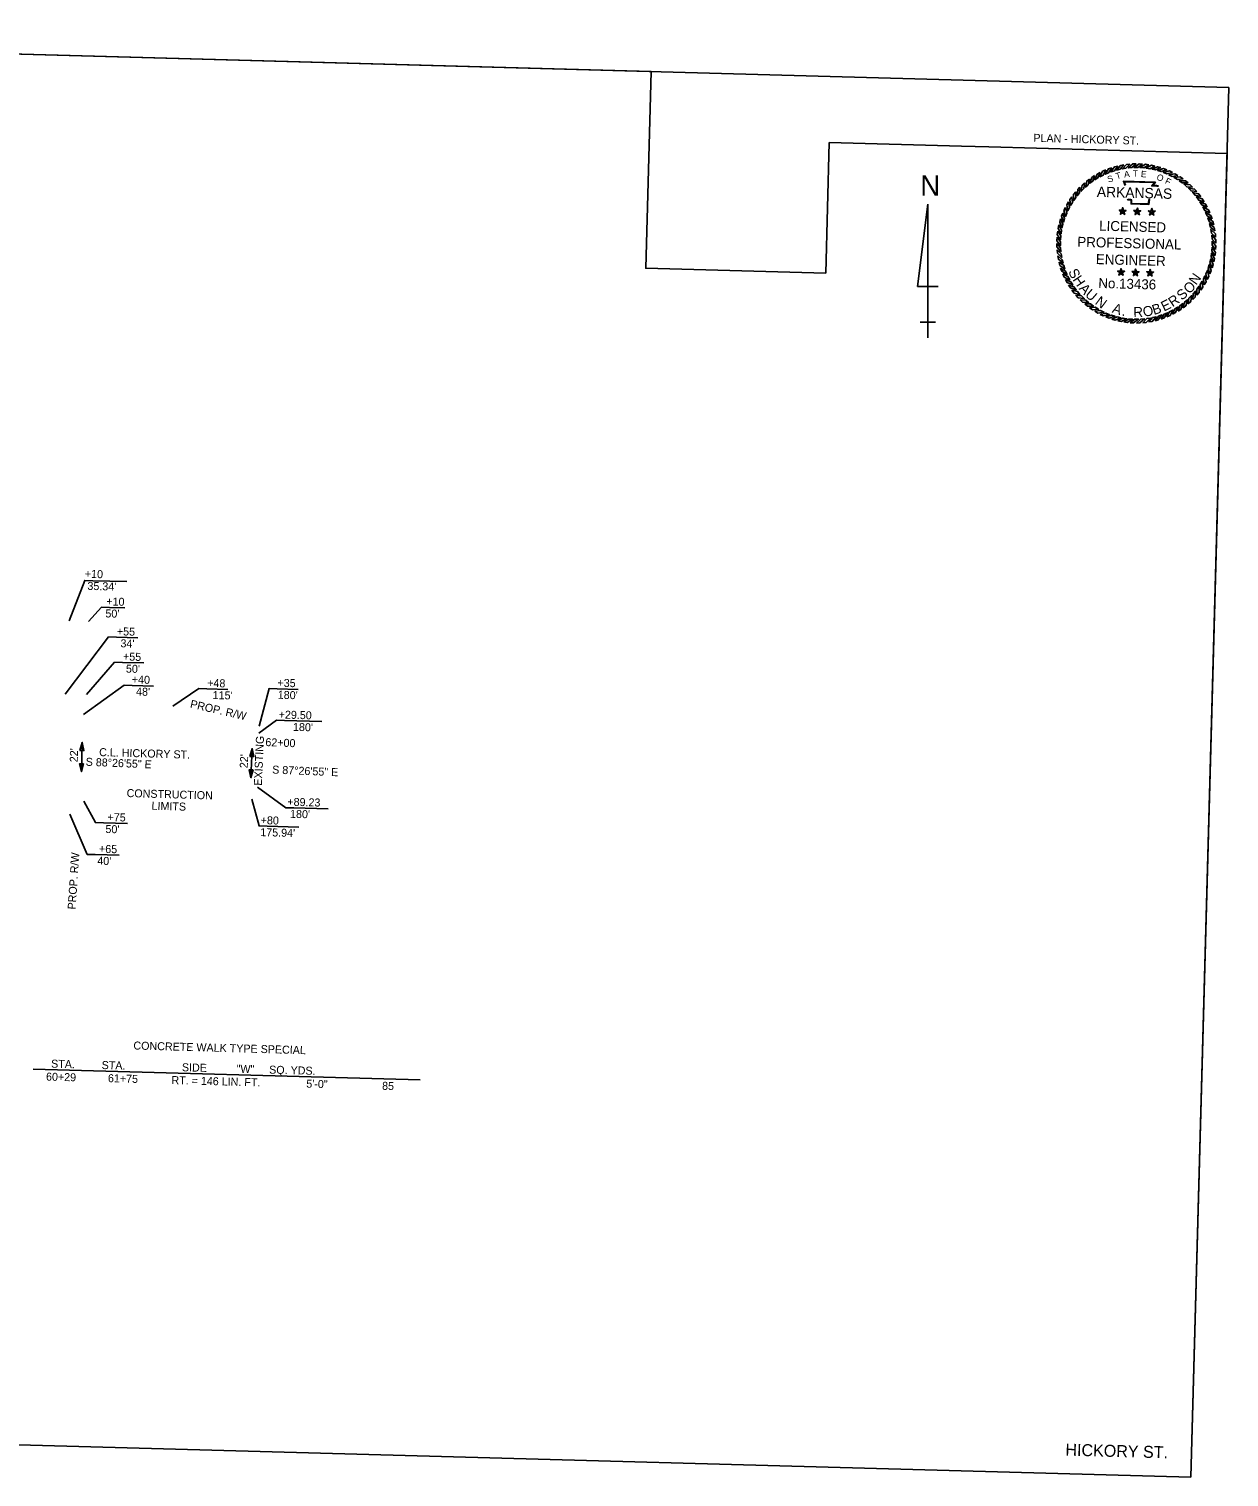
# Model space of a CAD drawing. Extents: x 991810 to 993433, y 1843620 to 1844706.
# Drawn here: x 992534 to 993433, y 1843620 to 1844706 of the extents above; entities that cross this region are included whole.
import ezdxf

# ---------------------------------------------------------------- set-up
doc = ezdxf.new("R2010")
doc.units = 0
for name, color, linetype in [('63', 7, 'Continuous'), ('8', 7, 'Continuous'), ('G-ANNO-SYMB', 7, 'Continuous'), ('G-ANNO-TEXT', 7, 'Continuous'), ('G-Border-Sheet', 7, 'Continuous'), ('G-No Plot-Border-2', 7, 'Continuous'), ('R_Draft', 7, 'Continuous'), ('R_Horz Alg Stationing', 7, 'Continuous')]:
    doc.layers.add(name, color=color, linetype=linetype)

msp = doc.modelspace()

# ---------------------------------------------------------------- linework, layer by layer
at = {"layer": '63'}
for p, q in [((993207.4, 1844574.4), (993199.7, 1844512.9)), ((993207.4, 1844474.4), (993207.4, 1844574.4)), ((993207.4, 1844574.4), (993207.4, 1844497.5)), ((993199.7, 1844512.9), (993215.1, 1844512.9)), ((993207.4, 1844474.4), (993207.4, 1844497.5)), ((993207.4, 1844486), (993201.6, 1844486)), ((993201.6, 1844486), (993213.2, 1844486)), ((993207.4, 1844474.4), (993207.4, 1844486))]:
    msp.add_line(p, q, dxfattribs=at)
at = {"layer": '8'}
msp.add_line((992536.8, 1843925.9), (992826.8, 1843917.9), dxfattribs=at)
at = {"layer": 'G-ANNO-SYMB'}
for points in [[(993345.3, 1844601.8), (993342.8, 1844601), (993340.5, 1844597), (993343, 1844598.1)], [(993349.8, 1844603.1), (993347.3, 1844602.4), (993344.6, 1844598.7), (993347.3, 1844599.6)], [(993354.4, 1844604), (993351.8, 1844603.5), (993348.9, 1844600.1), (993351.6, 1844600.7)], [(993359, 1844604.6), (993356.5, 1844604.3), (993353.3, 1844601), (993356, 1844601.5)], [(993363.7, 1844604.8), (993361.1, 1844604.7), (993357.7, 1844601.7), (993360.4, 1844601.9)], [(993368.4, 1844604.6), (993365.8, 1844604.7), (993362.1, 1844602), (993364.9, 1844602)], [(993373, 1844604), (993370.5, 1844604.4), (993366.6, 1844602), (993369.4, 1844601.7)], [(993377.6, 1844603.1), (993375.1, 1844603.7), (993371.1, 1844601.6), (993373.8, 1844601.1)], [(993382.1, 1844601.9), (993379.7, 1844602.6), (993375.5, 1844600.8), (993378.2, 1844600.2)], [(993386.5, 1844600.2), (993384.1, 1844601.2), (993379.8, 1844599.7), (993382.4, 1844598.9)], [(993325, 1844590.4), (993323.1, 1844588.7), (993322.4, 1844584.2), (993324.3, 1844586.2)], [(993328.6, 1844593.3), (993326.6, 1844591.8), (993325.6, 1844587.3), (993327.7, 1844589.1)], [(993332.5, 1844595.9), (993330.4, 1844594.5), (993329, 1844590.2), (993331.2, 1844591.8)], [(993336.6, 1844598.2), (993334.4, 1844597), (993332.6, 1844592.8), (993335, 1844594.2)], [(993340.9, 1844600.2), (993338.5, 1844599.2), (993336.5, 1844595.1), (993338.9, 1844596.3)], [(993390.8, 1844598.3), (993388.5, 1844599.4), (993384, 1844598.3), (993386.6, 1844597.2)], [(993394.9, 1844596), (993392.7, 1844597.3), (993388.2, 1844596.5), (993390.6, 1844595.3)], [(993398.8, 1844593.4), (993396.7, 1844594.9), (993392.1, 1844594.5), (993394.5, 1844593)], [(993402.5, 1844590.5), (993400.5, 1844592.1), (993395.9, 1844592.1), (993398.1, 1844590.5)], [(993315.5, 1844580.1), (993314, 1844578), (993314.4, 1844573.4), (993315.8, 1844575.8)], [(993318.4, 1844583.8), (993316.7, 1844581.8), (993316.8, 1844577.2), (993318.4, 1844579.5)], [(993321.5, 1844587.2), (993319.8, 1844585.4), (993319.4, 1844580.8), (993321.2, 1844582.9)], [(993405.9, 1844587.3), (993404, 1844589.1), (993399.5, 1844589.4), (993401.6, 1844587.6)], [(993409.1, 1844583.9), (993407.4, 1844585.8), (993402.9, 1844586.5), (993404.8, 1844584.5)], [(993412, 1844580.2), (993410.4, 1844582.3), (993406, 1844583.3), (993407.8, 1844581.2)], [(993414.6, 1844576.3), (993413.2, 1844578.5), (993408.8, 1844579.9), (993410.5, 1844577.6)], [(993310.6, 1844572.1), (993309.5, 1844569.8), (993310.6, 1844565.4), (993311.6, 1844567.9)], [(993312.9, 1844576.2), (993311.6, 1844574), (993312.3, 1844569.5), (993313.6, 1844572)], [(993353.5, 1844569.1), (993352.9, 1844570), (993350.9, 1844570.1), (993352.5, 1844568.8)], [(993353.5, 1844569.1), (993352.5, 1844568.8), (993351.8, 1844567), (993353.5, 1844568.1)], [(993353.5, 1844569.1), (993354.1, 1844570), (993353.6, 1844571.9), (993352.9, 1844570)], [(993353.5, 1844569.1), (993354.5, 1844568.8), (993356.1, 1844569.9), (993354.1, 1844570)], [(993353.5, 1844569.1), (993353.5, 1844568.1), (993355.1, 1844566.9), (993354.5, 1844568.8)], [(993364.4, 1844568.8), (993363.8, 1844569.7), (993361.8, 1844569.8), (993363.4, 1844568.5)], [(993364.4, 1844568.8), (993363.4, 1844568.5), (993362.8, 1844566.7), (993364.4, 1844567.8)], [(993364.4, 1844568.8), (993365.1, 1844569.7), (993364.5, 1844571.6), (993363.8, 1844569.7)], [(993364.4, 1844568.8), (993365.4, 1844568.5), (993367, 1844569.6), (993365.1, 1844569.7)], [(993364.4, 1844568.8), (993364.4, 1844567.8), (993366, 1844566.6), (993365.4, 1844568.5)], [(993375.3, 1844568.5), (993374.7, 1844569.4), (993372.8, 1844569.5), (993374.3, 1844568.2)], [(993375.3, 1844568.5), (993374.3, 1844568.2), (993373.7, 1844566.4), (993375.3, 1844567.5)], [(993375.3, 1844568.5), (993376, 1844569.4), (993375.4, 1844571.3), (993374.7, 1844569.4)], [(993375.3, 1844568.5), (993376.3, 1844568.2), (993377.9, 1844569.3), (993376, 1844569.4)], [(993375.3, 1844568.5), (993375.3, 1844567.5), (993376.9, 1844566.3), (993376.3, 1844568.2)], [(993416.9, 1844572.2), (993415.7, 1844574.5), (993411.4, 1844576.2), (993412.9, 1844573.9)], [(993418.9, 1844568), (993417.8, 1844570.3), (993413.7, 1844572.4), (993415, 1844569.9)], [(993305.7, 1844559), (993305.2, 1844556.4), (993307.3, 1844552.4), (993307.7, 1844555.1)], [(993307, 1844563.5), (993306.3, 1844561), (993308, 1844556.8), (993308.7, 1844559.5)], [(993308.6, 1844567.9), (993307.7, 1844565.5), (993309.1, 1844561.1), (993310, 1844563.8)], [(993420.5, 1844563.6), (993419.6, 1844566), (993415.7, 1844568.4), (993416.8, 1844565.8)], [(993421.8, 1844559.1), (993421.1, 1844561.6), (993417.4, 1844564.2), (993418.3, 1844561.6)], [(993422.7, 1844554.5), (993422.2, 1844557), (993418.7, 1844560), (993419.4, 1844557.3)], [(993304.3, 1844549.7), (993304.1, 1844547.1), (993306.9, 1844543.5), (993306.8, 1844546.2)], [(993304.8, 1844554.4), (993304.5, 1844551.8), (993306.9, 1844547.9), (993307.1, 1844550.7)], [(993423.2, 1844549.8), (993423, 1844552.4), (993419.7, 1844555.6), (993420.2, 1844552.9)], [(993423.4, 1844545.2), (993423.4, 1844547.7), (993420.4, 1844551.2), (993420.6, 1844548.4)], [(993304.1, 1844545), (993304.2, 1844542.5), (993307.2, 1844539), (993306.9, 1844541.8)], [(993304.3, 1844540.3), (993304.6, 1844537.8), (993307.8, 1844534.6), (993307.4, 1844537.3)], [(993421.8, 1844531.2), (993422.3, 1844533.7), (993420.2, 1844537.8), (993419.8, 1844535.1)], [(993422.7, 1844535.8), (993423, 1844538.4), (993420.6, 1844542.2), (993420.4, 1844539.5)], [(993423.2, 1844540.5), (993423.4, 1844543), (993420.7, 1844546.7), (993420.7, 1844543.9)], [(993304.8, 1844535.7), (993305.3, 1844533.2), (993308.8, 1844530.2), (993308.1, 1844532.9)], [(993305.8, 1844531.1), (993306.4, 1844528.6), (993310.1, 1844526), (993309.3, 1844528.6)], [(993307, 1844526.6), (993307.9, 1844524.2), (993311.8, 1844521.8), (993310.7, 1844524.4)], [(993352.3, 1844523.5), (993352.9, 1844524.3), (993352.3, 1844526.2), (993351.7, 1844524.3)], [(993363.2, 1844523.2), (993363.8, 1844524), (993363.2, 1844525.9), (993362.6, 1844524)], [(993374.1, 1844522.9), (993374.7, 1844523.7), (993374.1, 1844525.6), (993373.5, 1844523.7)], [(993418.9, 1844522.3), (993419.8, 1844524.7), (993418.4, 1844529.1), (993417.5, 1844526.4)], [(993420.5, 1844526.7), (993421.3, 1844529.2), (993419.5, 1844533.4), (993418.8, 1844530.7)], [(993308.7, 1844522.2), (993309.7, 1844519.9), (993313.8, 1844517.8), (993312.5, 1844520.3)], [(993310.6, 1844518), (993311.9, 1844515.7), (993316.1, 1844514), (993314.6, 1844516.3)], [(993352.3, 1844523.5), (993351.7, 1844524.3), (993349.7, 1844524.4), (993351.3, 1844523.2)], [(993352.3, 1844523.5), (993351.3, 1844523.2), (993350.6, 1844521.3), (993352.2, 1844522.4)], [(993352.3, 1844523.5), (993352.2, 1844522.4), (993353.8, 1844521.2), (993353.2, 1844523.1)], [(993352.3, 1844523.5), (993353.2, 1844523.1), (993354.9, 1844524.2), (993352.9, 1844524.3)], [(993363.2, 1844523.2), (993362.6, 1844524), (993360.6, 1844524.1), (993362.2, 1844522.9)], [(993363.2, 1844523.2), (993362.2, 1844522.9), (993361.5, 1844521), (993363.1, 1844522.1)], [(993363.2, 1844523.2), (993363.1, 1844522.1), (993364.7, 1844520.9), (993364.1, 1844522.8)], [(993363.2, 1844523.2), (993364.1, 1844522.8), (993365.8, 1844523.9), (993363.8, 1844524)], [(993374.1, 1844522.9), (993373.5, 1844523.7), (993371.5, 1844523.8), (993373.1, 1844522.6)], [(993374.1, 1844522.9), (993373.1, 1844522.6), (993372.4, 1844520.7), (993374, 1844521.8)], [(993374.1, 1844522.9), (993374, 1844521.8), (993375.6, 1844520.6), (993375, 1844522.5)], [(993374.1, 1844522.9), (993375, 1844522.5), (993376.7, 1844523.6), (993374.7, 1844523.7)], [(993412.1, 1844510.1), (993413.5, 1844512.2), (993413.1, 1844516.7), (993411.7, 1844514.4)], [(993414.7, 1844514), (993416, 1844516.2), (993415.2, 1844520.7), (993414, 1844518.2)], [(993416.9, 1844518.1), (993418.1, 1844520.4), (993417, 1844524.8), (993415.9, 1844522.3)], [(993312.9, 1844513.9), (993314.3, 1844511.7), (993318.7, 1844510.3), (993317, 1844512.6)], [(993315.5, 1844510), (993317.1, 1844507.9), (993321.5, 1844506.9), (993319.7, 1844509)], [(993318.4, 1844506.3), (993320.1, 1844504.4), (993324.7, 1844503.7), (993322.7, 1844505.7)], [(993402.6, 1844499.8), (993404.5, 1844501.5), (993405.2, 1844506), (993403.2, 1844504)], [(993406, 1844503), (993407.8, 1844504.8), (993408.1, 1844509.4), (993406.3, 1844507.3)], [(993409.2, 1844506.4), (993410.8, 1844508.4), (993410.8, 1844513), (993409.1, 1844510.7)], [(993321.6, 1844502.9), (993323.5, 1844501.1), (993328, 1844500.8), (993325.9, 1844502.6)], [(993325.1, 1844499.7), (993327.1, 1844498.1), (993331.6, 1844498.1), (993329.4, 1844499.7)], [(993328.7, 1844496.8), (993330.9, 1844495.3), (993335.4, 1844495.7), (993333, 1844497.2)], [(993332.6, 1844494.2), (993334.9, 1844492.9), (993339.4, 1844493.6), (993336.9, 1844494.9)], [(993336.7, 1844491.9), (993339, 1844490.8), (993343.5, 1844491.9), (993340.9, 1844492.9)], [(993382.3, 1844488.4), (993384.7, 1844489.2), (993387, 1844493.1), (993384.5, 1844492.1)], [(993386.7, 1844490), (993389, 1844491), (993391, 1844495.1), (993388.6, 1844493.9)], [(993390.9, 1844492), (993393.2, 1844493.2), (993394.9, 1844497.4), (993392.5, 1844496)], [(993395, 1844494.3), (993397.1, 1844495.6), (993398.5, 1844500), (993396.3, 1844498.4)], [(993398.9, 1844496.9), (993400.9, 1844498.4), (993402, 1844502.9), (993399.9, 1844501.1)], [(993341, 1844490), (993343.4, 1844489), (993347.7, 1844490.5), (993345.1, 1844491.3)], [(993345.4, 1844488.3), (993347.8, 1844487.6), (993352.1, 1844489.4), (993349.4, 1844490)], [(993349.9, 1844487.1), (993352.4, 1844486.5), (993356.5, 1844488.6), (993353.7, 1844489.1)], [(993354.5, 1844486.2), (993357, 1844485.8), (993360.9, 1844488.2), (993358.2, 1844488.4)], [(993359.1, 1844485.6), (993361.7, 1844485.5), (993365.4, 1844488.2), (993362.6, 1844488.2)], [(993363.8, 1844485.4), (993366.4, 1844485.5), (993369.8, 1844488.5), (993367.1, 1844488.3)], [(993368.5, 1844485.6), (993371.1, 1844485.9), (993374.3, 1844489.1), (993371.5, 1844488.7)], [(993373.2, 1844486.2), (993375.7, 1844486.6), (993378.6, 1844490.1), (993375.9, 1844489.5)], [(993377.8, 1844487.1), (993380.2, 1844487.8), (993382.9, 1844491.5), (993380.3, 1844490.6)]]:
    msp.add_lwpolyline(points, close=True, dxfattribs=at)
for points in [[(993355.4, 1844588.6), (993354.1, 1844591.7), (993378.1, 1844591), (993376.1, 1844588.6), (993377.7, 1844588.5), (993379.1, 1844588.5), (993380.4, 1844588.3)], [(993355.7, 1844588.8), (993354.7, 1844591.3), (993377.3, 1844590.7), (993375.3, 1844588.2), (993377.7, 1844588.2), (993379, 1844588.1), (993380.4, 1844588)], [(993374, 1844578), (993373.6, 1844577.7), (993373.4, 1844577.2), (993373.3, 1844576), (993373.2, 1844574.3), (993359.8, 1844574.7), (993359.8, 1844576.9), (993359.9, 1844577.4), (993359.3, 1844577.6), (993357.4, 1844577.7), (993357.1, 1844578.2)], [(993373.8, 1844578.3), (993373.2, 1844577.9), (993373.1, 1844577.3), (993372.9, 1844576), (993372.8, 1844574.7), (993360.2, 1844575.1), (993360.2, 1844576.9), (993360.2, 1844577.7), (993359.4, 1844578), (993357.6, 1844578), (993357.4, 1844578.4)]]:
    msp.add_lwpolyline(points, dxfattribs=at)
at = {"layer": 'G-Border-Sheet'}
for p in [(991838.5, 1844705.9), (993418.9, 1844141.1)]:
    msp.add_line(p, (993433.2, 1844662), dxfattribs=at)
msp.add_lwpolyline([(993418.9, 1844141.1), (993404.6, 1843620.1), (991809.8, 1843664), (991824.1, 1844184.9)], dxfattribs=at)
at = {"layer": 'G-No Plot-Border-2'}
msp.add_lwpolyline([(991809.8, 1843664), (991838.5, 1844705.9), (993000, 1844673.9), (992996, 1844526.5), (993130.9, 1844522.8), (993133.6, 1844620.7), (993232.8, 1844618), (993253.3, 1844617.4), (993431.9, 1844612.5), (993404.6, 1843620.1)], close=True, dxfattribs=at)
at = {"layer": 'R_Draft'}
for p, q in [((992607, 1844291.5), (992581.5, 1844292.2)), ((992605.5, 1844271.8), (992594, 1844272.1)), ((992615.2, 1844249.4), (992599.4, 1844249.8)), ((992619.7, 1844230.5), (992603.9, 1844230.9)), ((992626.9, 1844213.2), (992611.1, 1844213.7)), ((992682.8, 1844210.7), (992667.1, 1844211.1)), ((992735.5, 1844210.7), (992719.7, 1844211.2)), ((992753.2, 1844186.5), (992725.3, 1844187.3)), ((992573.6, 1844170.9), (992573, 1844148.9)), ((992701, 1844166.3), (992700, 1844144.4)), ((992757.9, 1844121.1), (992732.3, 1844121.8)), ((992607.5, 1844110.1), (992589.5, 1844110.6)), ((992736, 1844107.4), (992712.2, 1844108.1)), ((992601.4, 1844086.3), (992583.3, 1844086.8))]:
    msp.add_line(p, q, dxfattribs=at)
for points in [[(992563.7, 1844262.1), (992575.5, 1844292.4), (992581.5, 1844292.2)], [(992578.4, 1844261.7), (992588, 1844272.3), (992594, 1844272.1)], [(992560.9, 1844207.2), (992593.4, 1844250), (992599.4, 1844249.8)], [(992576.9, 1844206.8), (992597.9, 1844231.1), (992603.9, 1844230.9)], [(992574.5, 1844191.8), (992605.1, 1844213.8), (992611.1, 1844213.7)], [(992641.6, 1844198), (992661.1, 1844211.3), (992667.1, 1844211.1)], [(992706.3, 1844183.2), (992713.7, 1844211.3), (992719.7, 1844211.2)], [(992706.1, 1844177.8), (992719.3, 1844187.5), (992725.3, 1844187.3)], [(992705, 1844137.5), (992726.3, 1844122), (992732.3, 1844121.8)], [(992574.7, 1844126.8), (992583.5, 1844110.8), (992589.5, 1844110.6)], [(992700.7, 1844128.4), (992706.2, 1844108.3), (992712.2, 1844108.1)], [(992564.4, 1844117.1), (992577.3, 1844087), (992583.3, 1844086.8)]]:
    msp.add_lwpolyline(points, dxfattribs=at)
for points in [[(992571.9, 1844164.9), (992573.6, 1844170.9), (992574.9, 1844164.8)], [(992699.2, 1844160.4), (992701, 1844166.3), (992702.2, 1844160.3)], [(992574.6, 1844154.8), (992573, 1844148.9), (992571.6, 1844154.9)], [(992701.8, 1844150.3), (992700, 1844144.4), (992698.8, 1844150.4)]]:
    msp.add_lwpolyline(points, close=True, dxfattribs=at)

# ---------------------------------------------------------------- texts
at = {"layer": '63'}
msp.add_text('N', height=15.4, rotation=0, dxfattribs=at).set_placement((993201.8, 1844580.8))
at = {"layer": '8'}
for s, p in [('CONCRETE WALK TYPE SPECIAL', (992611.9, 1843940.7)), ('STA.         STA.                   SIDE          "W"     SQ. YDS.', (992550.2, 1843927.1)), ('60+29', (992546.4, 1843917.4)), ('61+75', (992592.8, 1843916.2)), ('RT. = 146 LIN. FT.', (992640.4, 1843914.8)), ('5\'-0"', (992741.5, 1843912.1)), ('85', (992798.3, 1843910.5))]:
    msp.add_text(s, height=6, rotation=358.4243, dxfattribs=at).set_placement(p)
at = {"layer": 'G-ANNO-SYMB'}
for s, height, rotation, p in [('S', 4.75, 18.1969, (993342.9, 1844590.6)), ('T', 4.75, 15.3258, (993349, 1844593.1)), ('A', 4.75, 7.1031, (993354.8, 1844594.5)), ('T', 4.75, 359.9032, (993361, 1844595.2)), ('E', 4.75, 355.0964, (993367, 1844594.9)), ('O', 4.75, 339.6461, (993378.5, 1844593)), ('F', 4.75, 333.7871, (993384.8, 1844590.3)), ('ARKANSAS', 7.75, 358.4243, (993334.1, 1844580)), ('LICENSED', 7.5, 358.4243, (993335.8, 1844554.7)), ('PROFESSIONAL', 7.5, 358.4243, (993319.4, 1844542.6)), ('ENGINEER', 7.5, 358.4243, (993333.3, 1844529.6)), ('S', 7.5, 296.588, (993312.5, 1844523.9)), ('H', 7.5, 304.0434, (993315.7, 1844517.9)), ('No.13436', 7.47, 358.4243, (993335.2, 1844511.7)), ('O', 7.5, 43.2, (993403.3, 1844506.8)), ('N', 7.5, 54.525, (993408.6, 1844513.4)), ('A', 7.5, 311.8715, (993320.3, 1844511)), ('U', 7.5, 319.3269, (993324.8, 1844505.9)), ('N', 7.5, 323.3569, (993332.3, 1844500.1)), ('R', 7.5, 34.084, (993390.9, 1844497.1)), ('S', 7.5, 41.9122, (993398, 1844502)), ('A', 7.5, 341.5234, (993345.1, 1844493.4)), ('R', 7.5, 1.653, (993361.6, 1844489.8)), ('O', 7.5, 9.8539, (993369.3, 1844490)), ('B', 7.5, 17.3093, (993376.9, 1844491.4)), ('E', 7.5, 26.2558, (993384.5, 1844493.9)), ('.', 7.5, 349.7243, (993352.5, 1844491))]:
    msp.add_text(s, height=height, rotation=rotation, dxfattribs=at).set_placement(p)
at = {"layer": 'G-ANNO-TEXT'}
for s, height, p in [('PLAN - HICKORY ST.', 6, (993286.5, 1844621.3)), ('HICKORY ST.', 9, (993310.5, 1843636.2))]:
    msp.add_text(s, height=height, rotation=358.4243, dxfattribs=at).set_placement(p)
at = {"layer": 'R_Draft'}
for s, rotation, p in [('+10', 358.4243, (992575.5, 1844294.4)), (" 35.34'", 358.4243, (992575.2, 1844285.4)), ('+10', 358.4243, (992591.6, 1844273.7)), ("50'", 358.4243, (992590.9, 1844264.7)), ('+55', 358.4243, (992599.5, 1844251.3)), ("34'", 358.4243, (992602.2, 1844242.3)), ('+55', 358.4243, (992604.1, 1844232.4)), ("50'", 358.4243, (992606.3, 1844223.3)), ('+40', 358.4243, (992610.7, 1844215.2)), ("48'", 358.4243, (992613.9, 1844206.1)), ('+48', 358.4243, (992667.2, 1844212.6)), ('+35', 358.4243, (992719.9, 1844212.7)), ('PROP. R/W', 347.1387, (992654.1, 1844197.1)), ("115'", 358.4243, (992671.3, 1844203.5)), ("180'", 358.4243, (992720.1, 1844203.7)), ('+29.50', 358.4243, (992720.8, 1844188.9)), (" 180'", 358.4243, (992729.3, 1844179.7)), ('C.L. HICKORY ST.', 358.3352, (992586.2, 1844160.7)), ('EXISTING', 87.3629, (992708.2, 1844138.4)), ("22'", 88.3562, (992570.2, 1844156)), ('S 88%%d26\'55" E', 357.6013, (992576.1, 1844153.5)), ("22'", 87.3629, (992697.6, 1844151.5)), ('S 87%%d26\'55" E', 357.6013, (992715.9, 1844147.6)), ('CONSTRUCTION', 358.3357, (992606.8, 1844130)), ('LIMITS ', 358.3357, (992625.5, 1844120.5)), ('+89.23', 358.4243, (992727.3, 1844123.5)), ('+75', 358.4243, (992592.5, 1844112)), ('+80', 358.4243, (992707.3, 1844109.7)), (" 180'", 358.4243, (992727.1, 1844114.5)), (" 50'", 358.4243, (992588.7, 1844103.1)), ("175.94'", 358.4243, (992707, 1844100.7)), ('+65', 358.4243, (992586.1, 1844088.2)), ('PROP. R/W', 86.0963, (992568.6, 1844045.5)), (" 40'", 358.4243, (992582.6, 1844079.3))]:
    msp.add_text(s, height=6, rotation=rotation, dxfattribs=at).set_placement(p)
at = {"layer": 'R_Horz Alg Stationing'}
msp.add_text('62+00', height=6, rotation=357.7861, dxfattribs=at).set_placement((992710.8, 1844168.2))

doc.saveas('drawing.dxf')
